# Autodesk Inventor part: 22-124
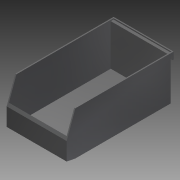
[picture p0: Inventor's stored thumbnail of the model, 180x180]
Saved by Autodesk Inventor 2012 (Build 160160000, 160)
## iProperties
Created: 2004-11
Part Number: 22-124
Document SubType Name: Modeling
Designer: Autodesk, Inc.
Manufacturer: Standard
Standards Organization: Custom
Description: Parts Bin, Conductive, Small
Vendor: PARKER IPS
Catalog Web Link: http://www.parker.com/ead/cm1.asp?cmid=809
Mass: 114.974 g
Surface Area: 1166.8 cm^2
Volume: 114.974 cm^3
Density: 1 g/cm^3
Material: Default
CAGE: 1LJX3
Dept. ID: Product Design
Description #2: ---
Finish #1: ---
Finish #2: ---
Material ID: ---
Project Number: ---
Author: Autodesk, Inc.
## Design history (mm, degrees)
sketch "Sketch2"
  geometry: L1 (-33.084, 98.5)-(-2.084, 98.5); L2 (-2.084, 98.5)-(40, 83.5); L3 (40, 83.5)-(40, -88.5); L4 (40, -88.5)-(28, -88.5); L5 (28, -88.5)-(28, -86.5); L6 (28, -86.5)-(36, -86.5); L7 (36, -86.5)-(36, -83.5); L8 (36, -83.5)-(-36, -83.5); L9 (-36, -83.5)-(-36, 83.5); L10 (-36, 83.5)-(-33.084, 98.5); 3 further points
  constraints: 20 end point, 5 parallel, 2 midpoint, 2 perpendicular, 1 horizontal, 1 horizontal alignment, 1 vertical alignment
  dimensions: "d0" = 15 vertical distance of L9.end L1.start; "d1" = 11 deg angle of L9 L10; "d2" = 31 distance of L1.start L1.end; "d4" = 2 distance of L4.end L5.end; "d5" = 3 distance between parallel lines of L8 L6; "d6" = 4 distance between parallel lines of L3 L7; "d7" = 12 distance of L3.end L4.end; "Dim_D" = 187 distance between parallel lines of L4 L1; "Dim_H" = 76 distance between parallel lines of L9 L3; "d11" = 19.6175 deg angle of L2 L1 (derived); "d12" = 15 vertical distance of L1.end L2.end
extrude "Extrusion1" new body sketch "Sketch2" taper "d14" = 0 deg; stored distance "Dim_W" = 105
shell "Shell1" dims "d18" = 2
body "Solid1"
